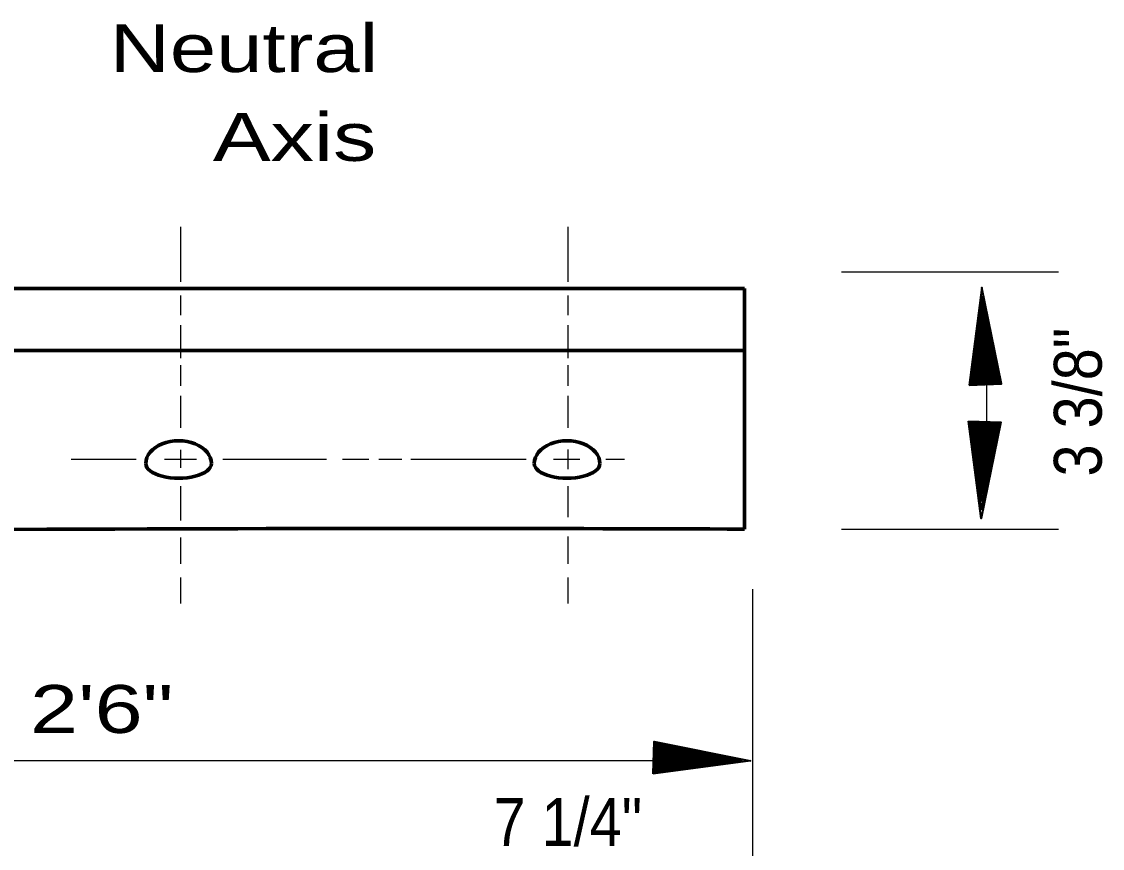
# Model space of a CAD drawing. Extents: x 895.6 to 930.4, y -2278.6 to -2254.7.
# Drawn here: x 917.21 to 920.113, y -2270.16 to -2267.94 of the extents above; entities that cross this region are included whole.
import ezdxf

# ---------------------------------------------------------------- set-up
doc = ezdxf.new("R2010")
doc.units = 0
doc.header["$LTSCALE"] = 0.051
doc.layers.add('1', color=7, linetype='Continuous', lineweight=70)
doc.layers.add('3', color=7, linetype='Continuous', lineweight=40)

msp = doc.modelspace()

# ---------------------------------------------------------------- hatches: boundary and pattern name
at = {"layer": '3'}
for points in [[(919.75525, -2268.91583), (919.842, -2268.91283), (919.78975, -2268.65442), (919.78975, -2268.65442)], [(919.75967, -2268.9145), (919.83767, -2268.91183), (919.79067, -2268.67925), (919.79067, -2268.67925)], [(919.7635, -2268.91333), (919.83367, -2268.91092), (919.79133, -2268.70158), (919.79133, -2268.70158)], [(919.767, -2268.91225), (919.83008, -2268.91008), (919.792, -2268.72158), (919.792, -2268.72158)], [(919.77, -2268.91133), (919.82683, -2268.90942), (919.79267, -2268.73967), (919.79267, -2268.73967)], [(919.77292, -2268.91033), (919.824, -2268.90867), (919.79317, -2268.756), (919.79317, -2268.756)], [(919.77542, -2268.90967), (919.82142, -2268.90817), (919.79367, -2268.77067), (919.79367, -2268.77067)], [(919.77767, -2268.90883), (919.81908, -2268.90758), (919.79417, -2268.78392), (919.79417, -2268.78392)], [(919.77967, -2268.90833), (919.81708, -2268.907), (919.79467, -2268.79575), (919.79467, -2268.79575)], [(919.78158, -2268.90758), (919.81525, -2268.9065), (919.79492, -2268.8065), (919.79492, -2268.8065)], [(919.78317, -2268.90717), (919.8135, -2268.90608), (919.79525, -2268.81608), (919.79525, -2268.81608)], [(919.78475, -2268.90675), (919.81192, -2268.90575), (919.79567, -2268.82475), (919.79567, -2268.82475)], [(919.786, -2268.90625), (919.81058, -2268.90542), (919.79583, -2268.83258), (919.79583, -2268.83258)], [(919.78733, -2268.90575), (919.80933, -2268.90525), (919.79608, -2268.8395), (919.79608, -2268.8395)], [(919.78833, -2268.9055), (919.80825, -2268.90483), (919.79625, -2268.84583), (919.79625, -2268.84583)], [(919.78942, -2268.90517), (919.80725, -2268.90467), (919.7965, -2268.85142), (919.7965, -2268.85142)], [(919.79033, -2268.90492), (919.80642, -2268.90442), (919.79675, -2268.85658), (919.79675, -2268.85658)], [(919.79117, -2268.90475), (919.8055, -2268.90425), (919.79692, -2268.86108), (919.79692, -2268.86108)], [(919.79158, -2268.90442), (919.80467, -2268.90408), (919.79692, -2268.86517), (919.79692, -2268.86517)], [(919.79217, -2268.90417), (919.80392, -2268.90383), (919.797, -2268.86883), (919.797, -2268.86883)], [(919.79267, -2268.90383), (919.80317, -2268.9035), (919.79683, -2268.87217), (919.79683, -2268.87217)], [(919.79325, -2268.90383), (919.80267, -2268.9035), (919.797, -2268.87525), (919.797, -2268.87525)], [(919.79375, -2268.90375), (919.80225, -2268.90333), (919.79717, -2268.87792), (919.79717, -2268.87792)], [(919.79417, -2268.9035), (919.80167, -2268.90325), (919.79717, -2268.88033), (919.79717, -2268.88033)], [(919.75367, -2269.01283), (919.84033, -2269.01575), (919.78817, -2269.27417), (919.78817, -2269.27417)], [(919.758, -2269.01408), (919.836, -2269.01683), (919.789, -2269.24942), (919.789, -2269.24942)], [(919.76192, -2269.01533), (919.832, -2269.01767), (919.78975, -2269.227), (919.78975, -2269.227)], [(919.76533, -2269.01633), (919.82842, -2269.0185), (919.79042, -2269.207), (919.79042, -2269.207)], [(919.76833, -2269.01725), (919.82517, -2269.01917), (919.791, -2269.18892), (919.791, -2269.18892)], [(919.77125, -2269.01833), (919.82233, -2269.01992), (919.7915, -2269.17267), (919.7915, -2269.17267)], [(919.77383, -2269.019), (919.81975, -2269.0205), (919.792, -2269.15792), (919.792, -2269.15792)], [(919.776, -2269.01983), (919.8175, -2269.02108), (919.7925, -2269.14467), (919.7925, -2269.14467)], [(919.778, -2269.02025), (919.81542, -2269.02158), (919.793, -2269.13292), (919.793, -2269.13292)], [(919.78, -2269.021), (919.81367, -2269.02217), (919.79333, -2269.12208), (919.79333, -2269.12208)], [(919.7815, -2269.02142), (919.81183, -2269.0225), (919.79358, -2269.1125), (919.79358, -2269.1125)], [(919.78308, -2269.02192), (919.81025, -2269.02292), (919.794, -2269.10392), (919.794, -2269.10392)], [(919.78442, -2269.02233), (919.80892, -2269.02317), (919.79425, -2269.096), (919.79425, -2269.096)], [(919.78567, -2269.02292), (919.80775, -2269.02342), (919.79442, -2269.08908), (919.79442, -2269.08908)], [(919.78675, -2269.02308), (919.80658, -2269.02375), (919.79458, -2269.08283), (919.79458, -2269.08283)], [(919.78775, -2269.0235), (919.80558, -2269.02392), (919.79492, -2269.07717), (919.79492, -2269.07717)], [(919.78867, -2269.02367), (919.80475, -2269.02425), (919.79508, -2269.07208), (919.79508, -2269.07208)], [(919.7895, -2269.02383), (919.80392, -2269.02442), (919.79525, -2269.0675), (919.79525, -2269.0675)], [(919.78992, -2269.02425), (919.80308, -2269.0245), (919.79525, -2269.06342), (919.79525, -2269.06342)], [(919.7905, -2269.02442), (919.80233, -2269.02483), (919.79533, -2269.05975), (919.79533, -2269.05975)], [(919.791, -2269.02475), (919.80158, -2269.02517), (919.79517, -2269.0565), (919.79517, -2269.0565)], [(919.79158, -2269.02475), (919.801, -2269.02517), (919.79533, -2269.05342), (919.79533, -2269.05342)], [(919.79208, -2269.02492), (919.80058, -2269.02525), (919.79558, -2269.05067), (919.79558, -2269.05067)], [(919.7925, -2269.02517), (919.80008, -2269.02533), (919.7955, -2269.04833), (919.7955, -2269.04833)], [(918.90642, -2269.95942), (918.90933, -2269.87275), (919.16775, -2269.92492), (919.16775, -2269.92492)], [(918.90767, -2269.95508), (918.91042, -2269.87708), (919.14292, -2269.92408), (919.14292, -2269.92408)], [(918.90892, -2269.95117), (918.91125, -2269.88108), (919.12058, -2269.92342), (919.12058, -2269.92342)], [(918.90992, -2269.94775), (918.91208, -2269.88467), (919.10058, -2269.92267), (919.10058, -2269.92267)], [(918.91083, -2269.94475), (918.91275, -2269.88792), (919.0825, -2269.92208), (919.0825, -2269.92208)], [(918.91192, -2269.94183), (918.9135, -2269.89075), (919.06625, -2269.92158), (919.06625, -2269.92158)], [(918.91258, -2269.93925), (918.91408, -2269.89333), (919.0515, -2269.92108), (919.0515, -2269.92108)], [(918.91342, -2269.93708), (918.91467, -2269.89567), (919.03825, -2269.92058), (919.03825, -2269.92058)], [(918.91383, -2269.93508), (918.91517, -2269.89767), (919.0265, -2269.92008), (919.0265, -2269.92008)], [(918.91458, -2269.93317), (918.91567, -2269.89942), (919.01567, -2269.91975), (919.01567, -2269.91975)], [(918.915, -2269.93158), (918.91608, -2269.90125), (919.00608, -2269.9195), (919.00608, -2269.9195)], [(918.9155, -2269.93), (918.91642, -2269.90283), (918.99742, -2269.91908), (918.99742, -2269.91908)], [(918.91592, -2269.92867), (918.91675, -2269.90417), (918.98958, -2269.91892), (918.98958, -2269.91892)], [(918.91642, -2269.92742), (918.917, -2269.90542), (918.98267, -2269.91867), (918.98267, -2269.91867)], [(918.91667, -2269.92642), (918.91733, -2269.9065), (918.97642, -2269.9185), (918.97642, -2269.9185)], [(918.91708, -2269.92533), (918.9175, -2269.9075), (918.97075, -2269.91817), (918.97075, -2269.91817)], [(918.91725, -2269.92442), (918.91783, -2269.90833), (918.96567, -2269.918), (918.96567, -2269.918)], [(918.91742, -2269.92358), (918.91792, -2269.90917), (918.96108, -2269.91783), (918.96108, -2269.91783)], [(918.91783, -2269.92317), (918.91808, -2269.91), (918.957, -2269.91783), (918.957, -2269.91783)], [(918.918, -2269.92258), (918.91842, -2269.91075), (918.95333, -2269.91775), (918.95333, -2269.91775)], [(918.91833, -2269.92208), (918.91867, -2269.9115), (918.95008, -2269.91792), (918.95008, -2269.91792)], [(918.91833, -2269.9215), (918.91867, -2269.91208), (918.947, -2269.91775), (918.947, -2269.91775)], [(918.9185, -2269.921), (918.91883, -2269.9125), (918.94425, -2269.9175), (918.94425, -2269.9175)], [(918.91867, -2269.92058), (918.91892, -2269.913), (918.94192, -2269.91758), (918.94192, -2269.91758)]]:
    msp.add_hatch(color=256, dxfattribs=at).paths.add_polyline_path(points)

# ---------------------------------------------------------------- linework, layer by layer
at = {"layer": '1', "lineweight": 25}
for p, q in [((917.63767, -2268.63867), (917.63767, -2268.4915)), ((918.6785, -2268.63867), (918.6785, -2268.4915)), ((919.413, -2268.61175), (919.99592, -2268.61175)), ((917.63767, -2268.72792), (917.63767, -2268.67542)), ((918.6785, -2268.72792), (918.6785, -2268.67542)), ((917.63767, -2268.84408), (917.63767, -2268.755)), ((918.6785, -2268.84408), (918.6785, -2268.755)), ((919.80267, -2269.12725), (919.80267, -2268.81558)), ((917.63767, -2268.91767), (917.63767, -2268.8625)), ((918.6785, -2268.91767), (918.6785, -2268.8625)), ((917.63767, -2269.03108), (917.63767, -2268.94525)), ((918.6785, -2269.03108), (918.6785, -2268.94525)), ((917.63767, -2269.13842), (917.63767, -2269.08992)), ((918.6785, -2269.1415), (918.6785, -2269.08933)), ((917.3435, -2269.11483), (917.51758, -2269.11483)), ((917.59417, -2269.11483), (917.68, -2269.11483)), ((917.75042, -2269.11483), (918.02925, -2269.11483)), ((918.07208, -2269.11483), (918.14258, -2269.11483)), ((918.17017, -2269.11483), (918.23142, -2269.11483)), ((918.25592, -2269.11483), (918.56533, -2269.11483)), ((918.63883, -2269.11483), (918.70933, -2269.11483)), ((918.77983, -2269.11483), (918.82925, -2269.11483)), ((917.63767, -2269.27942), (917.63767, -2269.1875)), ((918.6785, -2269.27025), (918.6785, -2269.1875)), ((919.413, -2269.303), (919.99592, -2269.303)), ((917.63767, -2269.396), (917.63767, -2269.32542)), ((918.6785, -2269.396), (918.6785, -2269.32242)), ((917.63767, -2269.502), (917.63767, -2269.43275)), ((918.6785, -2269.502), (918.6785, -2269.43275)), ((919.17408, -2270.94408), (919.17408, -2269.46433)), ((915.21425, -2269.9235), (919.14633, -2269.9235))]:
    msp.add_line(p, q, dxfattribs=at)
at = {"layer": '1'}
for p, q in [((919.152, -2268.65675), (915.21342, -2268.65675)), ((919.152, -2269.30267), (919.152, -2268.65675)), ((919.152, -2268.82342), (915.21342, -2268.82342))]:
    msp.add_line(p, q, dxfattribs=at)
for centre, major_axis, ratio in [((917.63193, -2269.12685), (0.08819, 0), 0.696674), ((918.67534, -2269.12685), (0.08819, 0), 0.696674), ((917.63193, -2269.12685), (-0.08819, 0), 0.442883), ((918.67534, -2269.12685), (-0.08819, 0), 0.442883)]:
    msp.add_ellipse(centre, major_axis=major_axis, ratio=ratio, start_param=0, end_param=3.1415927, dxfattribs=at)
msp.add_spline([(919.152, -2269.30267), (917.08242, -2269.30392), (916.97917, -2269.30392), (917.07483, -2269.302), (916.62433, -2269.28875), (916.428, -2269.24342), (916.23667, -2269.188), (916.05308, -2269.11258), (915.93467, -2269.03183), (915.81633, -2268.921), (915.73833, -2268.81525)], degree=3, dxfattribs=at)
at = {"layer": '3'}
for points in [[(919.75525, -2268.91583), (919.842, -2268.91283), (919.78975, -2268.65442), (919.78975, -2268.65442)], [(919.75967, -2268.9145), (919.83767, -2268.91183), (919.79067, -2268.67925), (919.79067, -2268.67925)], [(919.7635, -2268.91333), (919.83367, -2268.91092), (919.79133, -2268.70158), (919.79133, -2268.70158)], [(919.767, -2268.91225), (919.83008, -2268.91008), (919.792, -2268.72158), (919.792, -2268.72158)], [(919.77, -2268.91133), (919.82683, -2268.90942), (919.79267, -2268.73967), (919.79267, -2268.73967)], [(919.77292, -2268.91033), (919.824, -2268.90867), (919.79317, -2268.756), (919.79317, -2268.756)], [(919.77542, -2268.90967), (919.82142, -2268.90817), (919.79367, -2268.77067), (919.79367, -2268.77067)], [(919.77767, -2268.90883), (919.81908, -2268.90758), (919.79417, -2268.78392), (919.79417, -2268.78392)], [(919.77967, -2268.90833), (919.81708, -2268.907), (919.79467, -2268.79575), (919.79467, -2268.79575)], [(919.78158, -2268.90758), (919.81525, -2268.9065), (919.79492, -2268.8065), (919.79492, -2268.8065)], [(919.78317, -2268.90717), (919.8135, -2268.90608), (919.79525, -2268.81608), (919.79525, -2268.81608)], [(919.78475, -2268.90675), (919.81192, -2268.90575), (919.79567, -2268.82475), (919.79567, -2268.82475)], [(919.786, -2268.90625), (919.81058, -2268.90542), (919.79583, -2268.83258), (919.79583, -2268.83258)], [(919.78733, -2268.90575), (919.80933, -2268.90525), (919.79608, -2268.8395), (919.79608, -2268.8395)], [(919.78833, -2268.9055), (919.80825, -2268.90483), (919.79625, -2268.84583), (919.79625, -2268.84583)], [(919.78942, -2268.90517), (919.80725, -2268.90467), (919.7965, -2268.85142), (919.7965, -2268.85142)], [(919.79033, -2268.90492), (919.80642, -2268.90442), (919.79675, -2268.85658), (919.79675, -2268.85658)], [(919.79117, -2268.90475), (919.8055, -2268.90425), (919.79692, -2268.86108), (919.79692, -2268.86108)], [(919.79158, -2268.90442), (919.80467, -2268.90408), (919.79692, -2268.86517), (919.79692, -2268.86517)], [(919.79217, -2268.90417), (919.80392, -2268.90383), (919.797, -2268.86883), (919.797, -2268.86883)], [(919.79267, -2268.90383), (919.80317, -2268.9035), (919.79683, -2268.87217), (919.79683, -2268.87217)], [(919.79325, -2268.90383), (919.80267, -2268.9035), (919.797, -2268.87525), (919.797, -2268.87525)], [(919.79375, -2268.90375), (919.80225, -2268.90333), (919.79717, -2268.87792), (919.79717, -2268.87792)], [(919.79417, -2268.9035), (919.80167, -2268.90325), (919.79717, -2268.88033), (919.79717, -2268.88033)], [(919.75367, -2269.01283), (919.84033, -2269.01575), (919.78817, -2269.27417), (919.78817, -2269.27417)], [(919.758, -2269.01408), (919.836, -2269.01683), (919.789, -2269.24942), (919.789, -2269.24942)], [(919.76192, -2269.01533), (919.832, -2269.01767), (919.78975, -2269.227), (919.78975, -2269.227)], [(919.76533, -2269.01633), (919.82842, -2269.0185), (919.79042, -2269.207), (919.79042, -2269.207)], [(919.76833, -2269.01725), (919.82517, -2269.01917), (919.791, -2269.18892), (919.791, -2269.18892)], [(919.77125, -2269.01833), (919.82233, -2269.01992), (919.7915, -2269.17267), (919.7915, -2269.17267)], [(919.77383, -2269.019), (919.81975, -2269.0205), (919.792, -2269.15792), (919.792, -2269.15792)], [(919.776, -2269.01983), (919.8175, -2269.02108), (919.7925, -2269.14467), (919.7925, -2269.14467)], [(919.778, -2269.02025), (919.81542, -2269.02158), (919.793, -2269.13292), (919.793, -2269.13292)], [(919.78, -2269.021), (919.81367, -2269.02217), (919.79333, -2269.12208), (919.79333, -2269.12208)], [(919.7815, -2269.02142), (919.81183, -2269.0225), (919.79358, -2269.1125), (919.79358, -2269.1125)], [(919.78308, -2269.02192), (919.81025, -2269.02292), (919.794, -2269.10392), (919.794, -2269.10392)], [(919.78442, -2269.02233), (919.80892, -2269.02317), (919.79425, -2269.096), (919.79425, -2269.096)], [(919.78567, -2269.02292), (919.80775, -2269.02342), (919.79442, -2269.08908), (919.79442, -2269.08908)], [(919.78675, -2269.02308), (919.80658, -2269.02375), (919.79458, -2269.08283), (919.79458, -2269.08283)], [(919.78775, -2269.0235), (919.80558, -2269.02392), (919.79492, -2269.07717), (919.79492, -2269.07717)], [(919.78867, -2269.02367), (919.80475, -2269.02425), (919.79508, -2269.07208), (919.79508, -2269.07208)], [(919.7895, -2269.02383), (919.80392, -2269.02442), (919.79525, -2269.0675), (919.79525, -2269.0675)], [(919.78992, -2269.02425), (919.80308, -2269.0245), (919.79525, -2269.06342), (919.79525, -2269.06342)], [(919.7905, -2269.02442), (919.80233, -2269.02483), (919.79533, -2269.05975), (919.79533, -2269.05975)], [(919.791, -2269.02475), (919.80158, -2269.02517), (919.79517, -2269.0565), (919.79517, -2269.0565)], [(919.79158, -2269.02475), (919.801, -2269.02517), (919.79533, -2269.05342), (919.79533, -2269.05342)], [(919.79208, -2269.02492), (919.80058, -2269.02525), (919.79558, -2269.05067), (919.79558, -2269.05067)], [(919.7925, -2269.02517), (919.80008, -2269.02533), (919.7955, -2269.04833), (919.7955, -2269.04833)], [(918.90642, -2269.95942), (918.90933, -2269.87275), (919.16775, -2269.92492), (919.16775, -2269.92492)], [(918.90767, -2269.95508), (918.91042, -2269.87708), (919.14292, -2269.92408), (919.14292, -2269.92408)], [(918.90892, -2269.95117), (918.91125, -2269.88108), (919.12058, -2269.92342), (919.12058, -2269.92342)], [(918.90992, -2269.94775), (918.91208, -2269.88467), (919.10058, -2269.92267), (919.10058, -2269.92267)], [(918.91083, -2269.94475), (918.91275, -2269.88792), (919.0825, -2269.92208), (919.0825, -2269.92208)], [(918.91192, -2269.94183), (918.9135, -2269.89075), (919.06625, -2269.92158), (919.06625, -2269.92158)], [(918.91258, -2269.93925), (918.91408, -2269.89333), (919.0515, -2269.92108), (919.0515, -2269.92108)], [(918.91342, -2269.93708), (918.91467, -2269.89567), (919.03825, -2269.92058), (919.03825, -2269.92058)], [(918.91383, -2269.93508), (918.91517, -2269.89767), (919.0265, -2269.92008), (919.0265, -2269.92008)], [(918.91458, -2269.93317), (918.91567, -2269.89942), (919.01567, -2269.91975), (919.01567, -2269.91975)], [(918.915, -2269.93158), (918.91608, -2269.90125), (919.00608, -2269.9195), (919.00608, -2269.9195)], [(918.9155, -2269.93), (918.91642, -2269.90283), (918.99742, -2269.91908), (918.99742, -2269.91908)], [(918.91592, -2269.92867), (918.91675, -2269.90417), (918.98958, -2269.91892), (918.98958, -2269.91892)], [(918.91642, -2269.92742), (918.917, -2269.90542), (918.98267, -2269.91867), (918.98267, -2269.91867)], [(918.91667, -2269.92642), (918.91733, -2269.9065), (918.97642, -2269.9185), (918.97642, -2269.9185)], [(918.91708, -2269.92533), (918.9175, -2269.9075), (918.97075, -2269.91817), (918.97075, -2269.91817)], [(918.91725, -2269.92442), (918.91783, -2269.90833), (918.96567, -2269.918), (918.96567, -2269.918)], [(918.91742, -2269.92358), (918.91792, -2269.90917), (918.96108, -2269.91783), (918.96108, -2269.91783)], [(918.91783, -2269.92317), (918.91808, -2269.91), (918.957, -2269.91783), (918.957, -2269.91783)], [(918.918, -2269.92258), (918.91842, -2269.91075), (918.95333, -2269.91775), (918.95333, -2269.91775)], [(918.91833, -2269.92208), (918.91867, -2269.9115), (918.95008, -2269.91792), (918.95008, -2269.91792)], [(918.91833, -2269.9215), (918.91867, -2269.91208), (918.947, -2269.91775), (918.947, -2269.91775)], [(918.9185, -2269.921), (918.91883, -2269.9125), (918.94425, -2269.9175), (918.94425, -2269.9175)], [(918.91867, -2269.92058), (918.91892, -2269.913), (918.94192, -2269.91758), (918.94192, -2269.91758)]]:
    msp.add_lwpolyline(points, close=True, dxfattribs=at)

# ---------------------------------------------------------------- texts
at = {"layer": '1'}
for s, width, p in [('Neutral', 1.3, (917.44708, -2268.07567)), ('Axis', 1.35, (917.72425, -2268.314)), ('2\'6"', 1.35, (917.23283, -2269.84992)), ('7 1/4"', 0.9, (918.47792, -2270.15325))]:
    msp.add_text(s, height=0.1286, dxfattribs=dict(at, width=width)).set_placement(p)
at = {"layer": '1', "width": 0.9}
msp.add_text('3 3/8"', height=0.1286, rotation=90, dxfattribs=at).set_placement((920.11158, -2269.16142))

doc.saveas('drawing.dxf')
